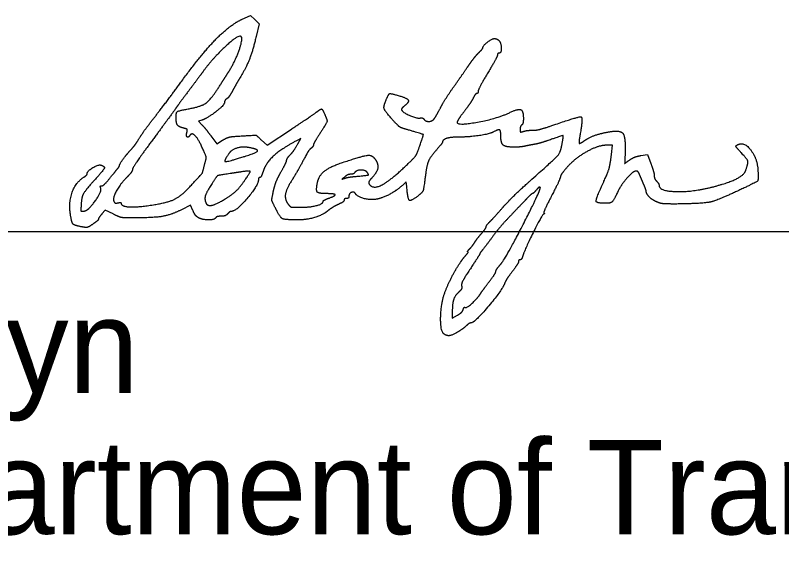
# Model space of a CAD drawing. Extents: x -6.1 to 38, y -7.7 to 22.
# Drawn here: x 26.554 to 27.692, y 4.883 to 5.697 of the extents above; entities that cross this region are included whole.
import ezdxf

# ---------------------------------------------------------------- set-up
doc = ezdxf.new("R2010")
doc.units = 0
for name, color, linetype in [('Default', 7, 'Continuous'), ('SH_Data', 7, 'Continuous'), ('SH_Text', 7, 'Continuous')]:
    doc.layers.add(name, color=color, linetype=linetype)

msp = doc.modelspace()

# ---------------------------------------------------------------- linework, layer by layer
at = {"layer": 'Default'}
for points in [[(26.8904, 5.6908), (26.903, 5.6966), (26.9094, 5.6903), (26.9158, 5.6839), (26.9114, 5.6652)], [(26.8305, 5.5408), (26.8255, 5.5392), (26.8306, 5.5341)], [(26.9194, 5.5111), (26.9276, 5.5035), (26.9638, 5.5276)], [(26.8443, 5.5174), (26.8528, 5.5059), (26.8616, 5.5111)], [(26.9733, 5.5058), (26.9778, 5.5138), (26.9723, 5.5108)], [(27.4392, 5.4899), (27.4407, 5.5037), (27.4329, 5.5037)], [(27.483, 5.4883), (27.4927, 5.4899), (27.4978, 5.4763)], [(27.1351, 5.4422), (27.1344, 5.449), (27.1286, 5.4439)], [(26.8175, 5.4066), (26.8141, 5.4146), (26.8003, 5.4077)], [(26.6988, 5.4015), (26.6873, 5.4073), (26.6823, 5.4015)], [(27.2028, 5.256), (27.2028, 5.2467), (27.2104, 5.251)]]:
    msp.add_lwpolyline(points, dxfattribs=at)
for points in [[(26.8008, 5.5989), (26.8305, 5.6395), (26.8723, 5.6824), (26.8904, 5.6908)], [(26.889, 5.665), (26.8853, 5.6686), (26.8468, 5.6329), (26.8314, 5.6116)], [(26.8707, 5.6129), (26.8801, 5.6278), (26.8921, 5.6619), (26.889, 5.665)], [(26.9114, 5.6652), (26.9064, 5.6441), (26.8972, 5.6205), (26.8878, 5.6045)], [(27.2484, 5.6489), (27.2484, 5.6517), (27.2616, 5.662), (27.2654, 5.6621)], [(27.2654, 5.6621), (27.2674, 5.6621), (27.2704, 5.6608), (27.272, 5.6593)], [(27.272, 5.6593), (27.2754, 5.6558), (27.2758, 5.6405), (27.2724, 5.6405)], [(27.2418, 5.6408), (27.2455, 5.6444), (27.2484, 5.648), (27.2484, 5.6489)], [(27.2281, 5.6235), (27.232, 5.6294), (27.2382, 5.6371), (27.2418, 5.6408)], [(27.27, 5.638), (27.27, 5.6366), (27.2636, 5.6245), (27.2556, 5.6111)], [(27.2724, 5.6405), (27.2711, 5.6405), (27.27, 5.6394), (27.27, 5.638)], [(27.2064, 5.5925), (27.2144, 5.6038), (27.2241, 5.6177), (27.2281, 5.6235)], [(26.8314, 5.6116), (26.8278, 5.6066), (26.8184, 5.594), (26.8104, 5.5835)], [(26.8601, 5.5963), (26.8634, 5.6015), (26.8681, 5.609), (26.8707, 5.6129)], [(26.8878, 5.6045), (26.8842, 5.5986), (26.879, 5.5894), (26.8762, 5.5841)], [(27.2556, 5.6111), (27.2477, 5.5978), (27.2412, 5.5854), (27.2412, 5.5837)], [(26.7607, 5.5455), (26.7696, 5.5568), (26.7876, 5.5809), (26.8008, 5.5989)], [(26.8103, 5.5576), (26.8309, 5.5613), (26.845, 5.5723), (26.8601, 5.5963)], [(27.1851, 5.5589), (27.1889, 5.5662), (27.1985, 5.5813), (27.2064, 5.5925)], [(26.8104, 5.5835), (26.8025, 5.573), (26.7944, 5.562), (26.7924, 5.5591)], [(26.8762, 5.5841), (26.8733, 5.5789), (26.8695, 5.5737), (26.8677, 5.5726)], [(27.1044, 5.5708), (27.1081, 5.5798), (27.1113, 5.5808), (27.124, 5.5771)], [(27.2393, 5.5805), (27.2382, 5.5805), (27.2358, 5.5776), (27.234, 5.5739)], [(27.2412, 5.5837), (27.2412, 5.5819), (27.2403, 5.5805), (27.2393, 5.5805)], [(26.8677, 5.5726), (26.8659, 5.5716), (26.8644, 5.5691), (26.8644, 5.5672)], [(27.1142, 5.5413), (27.1027, 5.5544), (27.1004, 5.5612), (27.1044, 5.5708)], [(27.124, 5.5771), (27.136, 5.5736), (27.1388, 5.5674), (27.1312, 5.5615)], [(27.234, 5.5739), (27.2322, 5.5703), (27.2261, 5.5612), (27.2204, 5.5537)], [(26.7924, 5.5591), (26.7905, 5.5561), (26.7751, 5.5352), (26.7583, 5.5125)], [(26.7924, 5.5455), (26.7924, 5.5523), (26.7966, 5.5551), (26.8103, 5.5576)], [(26.8644, 5.5672), (26.8644, 5.5634), (26.8387, 5.5434), (26.8305, 5.5408)], [(27.0029, 5.5541), (27.0075, 5.5579), (27.0099, 5.557), (27.0129, 5.5504)], [(27.1312, 5.5615), (27.1284, 5.5594), (27.127, 5.5566), (27.1279, 5.5553)], [(27.1758, 5.5427), (27.1771, 5.5444), (27.1812, 5.5517), (27.1851, 5.5589)], [(27.2876, 5.5519), (27.3006, 5.5581), (27.3084, 5.5549), (27.3084, 5.5435)], [(26.7391, 5.5161), (26.7421, 5.5209), (26.7518, 5.5341), (26.7607, 5.5455)], [(26.8034, 5.5291), (26.7963, 5.5309), (26.7924, 5.5366), (26.7924, 5.5455)], [(26.9638, 5.5276), (26.9837, 5.5409), (27.0013, 5.5528), (27.0029, 5.5541)], [(27.0129, 5.5504), (27.0172, 5.5408), (27.0163, 5.5367), (27.006, 5.5208)], [(27.1279, 5.5553), (27.1306, 5.5515), (27.1505, 5.5433), (27.1551, 5.5441)], [(27.2204, 5.5537), (27.2147, 5.5463), (27.21, 5.539), (27.21, 5.5377)], [(27.21, 5.5377), (27.21, 5.5324), (27.2697, 5.5433), (27.2876, 5.5519)], [(27.3508, 5.5328), (27.3911, 5.5467), (27.3971, 5.5451), (27.3929, 5.5212)], [(26.8306, 5.5341), (26.8335, 5.5313), (26.8396, 5.5238), (26.8443, 5.5174)], [(27.1376, 5.5262), (27.1269, 5.5293), (27.122, 5.5325), (27.1142, 5.5413)], [(27.1551, 5.5441), (27.1574, 5.5445), (27.1599, 5.5436), (27.1608, 5.5423)], [(27.1608, 5.5423), (27.1629, 5.5388), (27.173, 5.5391), (27.1758, 5.5427)], [(27.306, 5.5337), (27.3047, 5.5329), (27.3036, 5.5301), (27.3036, 5.5274)], [(27.3084, 5.5435), (27.3084, 5.539), (27.3074, 5.5346), (27.306, 5.5337)], [(26.8085, 5.5228), (26.8095, 5.5264), (26.8082, 5.5279), (26.8034, 5.5291)], [(26.8128, 5.5181), (26.8104, 5.5142), (26.8072, 5.5177), (26.8085, 5.5228)], [(27.1544, 5.5025), (27.1601, 5.5193), (27.1597, 5.5198), (27.1376, 5.5262)], [(27.2634, 5.5231), (27.2578, 5.5201), (27.2276, 5.5157), (27.2127, 5.5157)], [(27.2748, 5.5184), (27.2748, 5.5257), (27.2712, 5.5272), (27.2634, 5.5231)], [(27.3036, 5.5274), (27.3036, 5.5235), (27.3047, 5.5229), (27.309, 5.5243)], [(27.309, 5.5243), (27.312, 5.5253), (27.3178, 5.5259), (27.322, 5.5258)], [(27.322, 5.5258), (27.3261, 5.5256), (27.3391, 5.5288), (27.3508, 5.5328)], [(27.3989, 5.5103), (27.4061, 5.5154), (27.4244, 5.5217), (27.438, 5.5239)], [(27.438, 5.5239), (27.4527, 5.5262), (27.4603, 5.5157), (27.4596, 5.4945)], [(26.7228, 5.4942), (26.7294, 5.5015), (26.7337, 5.5073), (26.7391, 5.5161)], [(26.7583, 5.5125), (26.7415, 5.4899), (26.7277, 5.4697), (26.7276, 5.4677)], [(26.8316, 5.4994), (26.8255, 5.5131), (26.8157, 5.5228), (26.8128, 5.5181)], [(26.8616, 5.5111), (26.8682, 5.515), (26.8757, 5.5167), (26.8909, 5.5175)], [(26.8909, 5.5175), (26.9112, 5.5187), (26.9113, 5.5187), (26.9194, 5.5111)], [(26.9723, 5.5108), (26.9489, 5.4983), (26.9261, 5.4776), (26.922, 5.4652)], [(27.006, 5.5208), (27.0008, 5.5127), (26.9964, 5.5051), (26.9964, 5.5039)], [(27.2127, 5.5157), (27.2012, 5.5157), (27.1884, 5.512), (27.1884, 5.5086)], [(27.2942, 5.5008), (27.2818, 5.5008), (27.2748, 5.5071), (27.2748, 5.5184)], [(27.3454, 5.5108), (27.3376, 5.5081), (27.328, 5.5054), (27.324, 5.5048)], [(27.3661, 5.5062), (27.3682, 5.5177), (27.3664, 5.5181), (27.3454, 5.5108)], [(27.3929, 5.5212), (27.3916, 5.5136), (27.3909, 5.5069), (27.3913, 5.5065)], [(26.8349, 5.4749), (26.8375, 5.4848), (26.8372, 5.487), (26.8316, 5.4994)], [(26.9026, 5.4998), (26.8918, 5.502), (26.8744, 5.4969), (26.8701, 5.4903)], [(26.892, 5.4863), (26.9113, 5.4922), (26.9153, 5.4973), (26.9026, 5.4998)], [(26.9605, 5.4877), (26.966, 5.4937), (26.9685, 5.4973), (26.9733, 5.5058)], [(26.9964, 5.5039), (26.9964, 5.5028), (26.9948, 5.5006), (26.9929, 5.499)], [(27.1361, 5.4752), (27.1466, 5.4852), (27.1507, 5.4914), (27.1544, 5.5025)], [(27.1884, 5.5086), (27.1884, 5.5077), (27.1842, 5.5023), (27.1791, 5.4965)], [(27.3108, 5.5022), (27.3075, 5.5014), (27.3, 5.5008), (27.2942, 5.5008)], [(27.324, 5.5048), (27.3201, 5.5041), (27.3141, 5.503), (27.3108, 5.5022)], [(27.3212, 5.4532), (27.3567, 5.4848), (27.3636, 5.4929), (27.3661, 5.5062)], [(27.4329, 5.5037), (27.4202, 5.5037), (27.3864, 5.4853), (27.3742, 5.4718)], [(27.3913, 5.5065), (27.3918, 5.506), (27.3952, 5.5077), (27.3989, 5.5103)], [(27.6296, 5.4951), (27.6243, 5.5008), (27.6241, 5.5034), (27.6287, 5.5052)], [(27.6287, 5.5052), (27.6373, 5.5085), (27.6558, 5.4836), (27.6568, 5.4673)], [(26.7084, 5.4737), (26.7084, 5.4754), (26.7176, 5.4884), (26.7228, 5.4942)], [(26.8701, 5.4903), (26.8631, 5.4796), (26.8676, 5.4788), (26.892, 5.4863)], [(26.986, 5.4897), (26.9779, 5.4743), (26.9701, 5.4605), (26.964, 5.4508)], [(26.9929, 5.499), (26.9909, 5.4974), (26.9878, 5.4932), (26.986, 5.4897)], [(27.0398, 5.478), (27.0717, 5.4886), (27.0851, 5.489), (27.0902, 5.4795)], [(27.1791, 5.4965), (27.1706, 5.487), (27.1649, 5.4745), (27.1633, 5.4617)], [(27.4245, 5.4421), (27.4336, 5.462), (27.4376, 5.4752), (27.4392, 5.4899)], [(27.4596, 5.4945), (27.4589, 5.4761), (27.4588, 5.4764), (27.4665, 5.4819)], [(27.4665, 5.4819), (27.4703, 5.4846), (27.4777, 5.4875), (27.483, 5.4883)], [(27.6388, 5.466), (27.6427, 5.4778), (27.6412, 5.4827), (27.6296, 5.4951)], [(26.9481, 5.4636), (26.9525, 5.4713), (26.9563, 5.4789), (26.9566, 5.4807)], [(26.9566, 5.4807), (26.9568, 5.4824), (26.9586, 5.4856), (26.9605, 5.4877)], [(27.0022, 5.4469), (27.0043, 5.4582), (27.0205, 5.4716), (27.0398, 5.478)], [(27.0902, 5.4795), (27.0934, 5.4735), (27.09, 5.4621), (27.0825, 5.4542)], [(26.6605, 5.4617), (26.6605, 5.4655), (26.6773, 5.4754), (26.6811, 5.474)], [(26.6811, 5.474), (26.687, 5.4717), (26.6848, 5.4668), (26.6704, 5.4509)], [(26.6939, 5.4545), (26.6993, 5.4611), (26.7047, 5.4678), (26.706, 5.4694)], [(26.706, 5.4694), (26.7074, 5.471), (26.7084, 5.473), (26.7084, 5.4737)], [(26.7276, 5.4677), (26.7276, 5.4658), (26.7242, 5.4609), (26.7203, 5.457)], [(26.8152, 5.4444), (26.8313, 5.462), (26.8317, 5.4625), (26.8349, 5.4749)], [(26.8952, 5.4525), (26.9031, 5.4639), (26.9021, 5.466), (26.8902, 5.4642)], [(26.922, 5.4652), (26.9203, 5.46), (26.918, 5.4557), (26.9169, 5.4557)], [(27.076, 5.4638), (27.0732, 5.4671), (27.0597, 5.4663), (27.0575, 5.4627)], [(27.0791, 5.4463), (27.0845, 5.4377), (27.1112, 5.4512), (27.1361, 5.4752)], [(27.3742, 5.4718), (27.3684, 5.4653), (27.3636, 5.4587), (27.3636, 5.4572)], [(27.4761, 5.4653), (27.4717, 5.4653), (27.4535, 5.4448), (27.4488, 5.4347)], [(27.4816, 5.4587), (27.4802, 5.4624), (27.4777, 5.4653), (27.4761, 5.4653)], [(27.4978, 5.4763), (27.5006, 5.4689), (27.5028, 5.4607), (27.5028, 5.4582)], [(27.5899, 5.4417), (27.6136, 5.448), (27.6365, 5.4594), (27.6388, 5.466)], [(27.6568, 5.4673), (27.6577, 5.452), (27.655, 5.4489), (27.6316, 5.4379)], [(26.6356, 5.4001), (26.6326, 5.4186), (26.6434, 5.4486), (26.6558, 5.4564)], [(26.6558, 5.4564), (26.6583, 5.458), (26.6605, 5.4604), (26.6605, 5.4617)], [(26.6816, 5.4432), (26.6831, 5.4429), (26.6886, 5.4479), (26.6939, 5.4545)], [(26.7203, 5.457), (26.7104, 5.4474), (26.6981, 5.4253), (26.6999, 5.4206)], [(26.8728, 5.4615), (26.8551, 5.4589), (26.853, 5.4578), (26.8458, 5.4466)], [(26.8902, 5.4642), (26.8846, 5.4633), (26.8768, 5.4621), (26.8728, 5.4615)], [(26.9169, 5.4557), (26.9158, 5.4557), (26.9148, 5.4544), (26.9148, 5.4527)], [(26.9372, 5.4358), (26.9388, 5.4434), (26.9437, 5.456), (26.9481, 5.4636)], [(27.0431, 5.4567), (27.0385, 5.453), (27.0385, 5.453), (27.0432, 5.4546)], [(27.052, 5.4605), (27.0497, 5.4605), (27.0457, 5.4588), (27.0431, 5.4567)], [(27.0432, 5.4546), (27.0459, 5.4556), (27.0534, 5.4568), (27.06, 5.4574)], [(27.0575, 5.4627), (27.0568, 5.4615), (27.0543, 5.4605), (27.052, 5.4605)], [(27.06, 5.4574), (27.0768, 5.4589), (27.0792, 5.4599), (27.076, 5.4638)], [(27.0825, 5.4542), (27.0798, 5.4513), (27.0783, 5.4477), (27.0791, 5.4463)], [(27.1633, 5.4617), (27.1604, 5.4392), (27.1587, 5.4337), (27.153, 5.4293)], [(27.3636, 5.4572), (27.3636, 5.4556), (27.3577, 5.4427), (27.3504, 5.4286)], [(27.4876, 5.4446), (27.4858, 5.4487), (27.4831, 5.4551), (27.4816, 5.4587)], [(27.5028, 5.4582), (27.5028, 5.4557), (27.5045, 5.4521), (27.5064, 5.4501)], [(26.6704, 5.4509), (26.6568, 5.4357), (26.6518, 5.4256), (26.6512, 5.4118)], [(26.6804, 5.4403), (26.6797, 5.4423), (26.6802, 5.4436), (26.6816, 5.4432)], [(26.7587, 5.4151), (26.7815, 5.4188), (26.8011, 5.429), (26.8152, 5.4444)], [(26.8458, 5.4466), (26.8376, 5.4339), (26.8344, 5.4241), (26.8366, 5.4183)], [(26.8654, 5.4238), (26.8765, 5.4308), (26.8875, 5.4413), (26.8952, 5.4525)], [(26.9148, 5.4527), (26.9147, 5.4442), (26.8816, 5.4053), (26.8744, 5.4053)], [(26.964, 5.4508), (26.956, 5.4382), (26.9537, 5.423), (26.9589, 5.4162)], [(27.0158, 5.4317), (27.0043, 5.4317), (27.0002, 5.4363), (27.0022, 5.4469)], [(27.1286, 5.4439), (27.1192, 5.4357), (27.0992, 5.4251), (27.09, 5.4234)], [(27.2772, 5.4105), (27.2844, 5.4189), (27.3042, 5.4381), (27.3212, 5.4532)], [(27.4909, 5.435), (27.4909, 5.4361), (27.4894, 5.4404), (27.4876, 5.4446)], [(27.5064, 5.4501), (27.5084, 5.4481), (27.51, 5.4454), (27.51, 5.4441)], [(27.51, 5.4441), (27.51, 5.4355), (27.5606, 5.4341), (27.5899, 5.4417)], [(26.656, 5.4058), (26.6623, 5.4067), (26.6824, 5.4351), (26.6804, 5.4403)], [(26.9392, 5.4118), (26.9347, 5.4209), (26.9345, 5.4231), (26.9372, 5.4358)], [(27.0191, 5.4248), (27.0294, 5.4285), (27.0279, 5.4317), (27.0158, 5.4317)], [(27.0588, 5.4319), (27.0567, 5.4352), (27.0492, 5.432), (27.0492, 5.4279)], [(27.09, 5.4234), (27.0814, 5.4218), (27.0616, 5.4272), (27.0588, 5.4319)], [(27.153, 5.4293), (27.1413, 5.4201), (27.1369, 5.4232), (27.1351, 5.4422)], [(27.2746, 5.3267), (27.2822, 5.3354), (27.3354, 5.4391), (27.3334, 5.4412)], [(27.3219, 5.4317), (27.3211, 5.4317), (27.3172, 5.4282), (27.3131, 5.4239)], [(27.3277, 5.4371), (27.3252, 5.4342), (27.3226, 5.4317), (27.3219, 5.4317)], [(27.3334, 5.4412), (27.3326, 5.4419), (27.3301, 5.4401), (27.3277, 5.4371)], [(27.4319, 5.4173), (27.4173, 5.4173), (27.4157, 5.4228), (27.4245, 5.4421)], [(27.4488, 5.4347), (27.443, 5.4223), (27.4382, 5.4173), (27.4319, 5.4173)], [(27.5066, 5.4194), (27.4995, 5.4227), (27.4911, 5.4311), (27.4909, 5.435)], [(27.6316, 5.4379), (27.5968, 5.4216), (27.5758, 5.4168), (27.5364, 5.4163)], [(26.6999, 5.4206), (26.7008, 5.4182), (26.7031, 5.4173), (26.7061, 5.418)], [(26.8366, 5.4183), (26.8386, 5.413), (26.8522, 5.4156), (26.8654, 5.4238)], [(26.9764, 5.4114), (26.9904, 5.4113), (27.0108, 5.4164), (27.0108, 5.42)], [(27.0108, 5.42), (27.0108, 5.421), (27.0146, 5.4232), (27.0191, 5.4248)], [(27.042, 5.4221), (27.042, 5.4207), (27.0396, 5.4185), (27.0366, 5.4172)], [(27.0456, 5.4245), (27.0437, 5.4245), (27.042, 5.4234), (27.042, 5.4221)], [(27.0492, 5.4279), (27.0492, 5.426), (27.0476, 5.4245), (27.0456, 5.4245)], [(27.3131, 5.4239), (27.309, 5.4196), (27.2985, 5.4086), (27.2897, 5.3993)], [(27.3504, 5.4286), (27.3431, 5.4145), (27.338, 5.4029), (27.339, 5.4029)], [(26.6512, 5.4118), (26.6509, 5.4062), (26.6517, 5.4051), (26.656, 5.4058)], [(26.7061, 5.418), (26.7087, 5.4187), (26.7108, 5.4184), (26.7108, 5.4173)], [(26.7108, 5.4173), (26.7108, 5.4126), (26.7365, 5.4115), (26.7587, 5.4151)], [(26.9709, 5.3926), (26.9534, 5.3927), (26.9464, 5.3969), (26.9392, 5.4118)], [(26.9589, 5.4162), (26.9617, 5.4123), (26.9653, 5.4114), (26.9764, 5.4114)], [(27.0366, 5.4172), (27.0293, 5.4139), (27.0217, 5.4093), (27.0174, 5.4058)], [(27.2587, 5.3901), (27.2616, 5.3929), (27.2699, 5.4021), (27.2772, 5.4105)], [(27.5364, 5.4163), (27.5215, 5.4162), (27.5112, 5.4172), (27.5066, 5.4194)], [(26.6522, 5.3824), (26.6413, 5.3844), (26.6374, 5.3885), (26.6356, 5.4001)], [(26.6823, 5.4015), (26.6795, 5.3983), (26.6772, 5.3949), (26.6772, 5.3939)], [(26.7296, 5.3957), (26.714, 5.3957), (26.7081, 5.3968), (26.6988, 5.4015)], [(26.8003, 5.4077), (26.7847, 5.4), (26.7595, 5.3957), (26.7296, 5.3957)], [(26.8257, 5.3959), (26.823, 5.3974), (26.8193, 5.4021), (26.8175, 5.4066)], [(26.8595, 5.3981), (26.8558, 5.3981), (26.8521, 5.3971), (26.8512, 5.3957)], [(26.8692, 5.4017), (26.8676, 5.3998), (26.8632, 5.3981), (26.8595, 5.3981)], [(26.8744, 5.4053), (26.8732, 5.4053), (26.8709, 5.4037), (26.8692, 5.4017)], [(27.0174, 5.4058), (27.0098, 5.3995), (26.9854, 5.3925), (26.9709, 5.3926)], [(27.2897, 5.3993), (27.2808, 5.39), (27.2709, 5.3788), (27.2676, 5.3743)], [(27.3383, 5.4011), (27.3356, 5.3993), (27.3103, 5.3483), (27.3074, 5.3387)], [(27.339, 5.4029), (27.34, 5.4029), (27.3397, 5.4021), (27.3383, 5.4011)], [(26.6689, 5.3865), (26.6623, 5.382), (26.6587, 5.3811), (26.6522, 5.3824)], [(26.6772, 5.3939), (26.6772, 5.3929), (26.6735, 5.3896), (26.6689, 5.3865)], [(26.8512, 5.3957), (26.8493, 5.3925), (26.8318, 5.3927), (26.8257, 5.3959)], [(27.2533, 5.3829), (27.2533, 5.384), (27.2557, 5.3872), (27.2587, 5.3901)], [(27.2676, 5.3743), (27.2596, 5.3634), (27.2491, 5.3496), (27.2461, 5.346)], [(27.2466, 5.373), (27.2503, 5.3773), (27.2533, 5.3817), (27.2533, 5.3829)], [(27.2364, 5.3597), (27.2384, 5.3628), (27.243, 5.3688), (27.2466, 5.373)], [(27.2286, 5.3497), (27.231, 5.3522), (27.2345, 5.3567), (27.2364, 5.3597)], [(27.1927, 5.2873), (27.1985, 5.3022), (27.2157, 5.3321), (27.2228, 5.3399)], [(27.2228, 5.3399), (27.2255, 5.3429), (27.227, 5.3453), (27.2261, 5.3453)], [(27.2261, 5.3453), (27.2252, 5.3453), (27.2263, 5.3473), (27.2286, 5.3497)], [(27.2436, 5.3421), (27.2436, 5.3416), (27.2373, 5.3317), (27.2296, 5.32)], [(27.2461, 5.346), (27.2447, 5.3444), (27.2436, 5.3427), (27.2436, 5.3421)], [(27.3012, 5.3308), (27.3012, 5.3295), (27.297, 5.3227), (27.2918, 5.3158)], [(27.3035, 5.3333), (27.3023, 5.3333), (27.3012, 5.3322), (27.3012, 5.3308)], [(27.3074, 5.3387), (27.3065, 5.3358), (27.3047, 5.3333), (27.3035, 5.3333)], [(27.2296, 5.32), (27.2209, 5.307), (27.2159, 5.2972), (27.2167, 5.2945)], [(27.2676, 5.3164), (27.2676, 5.3177), (27.2708, 5.3223), (27.2746, 5.3267)], [(27.2574, 5.3005), (27.2631, 5.3079), (27.2676, 5.315), (27.2676, 5.3164)], [(27.2918, 5.3158), (27.2866, 5.3089), (27.2814, 5.3009), (27.2804, 5.2981)], [(27.2167, 5.2945), (27.2173, 5.292), (27.2158, 5.2884), (27.213, 5.2859)], [(27.2804, 5.2981), (27.2767, 5.2882), (27.2356, 5.2397), (27.2309, 5.2397)], [(27.2448, 5.2833), (27.2462, 5.2854), (27.2518, 5.2931), (27.2574, 5.3005)], [(27.1908, 5.2229), (27.1849, 5.2267), (27.1862, 5.271), (27.1927, 5.2873)], [(27.213, 5.2859), (27.207, 5.2807), (27.2028, 5.2684), (27.2028, 5.256)], [(27.222, 5.2625), (27.224, 5.2613), (27.2406, 5.2765), (27.2448, 5.2833)], [(27.219, 5.2595), (27.2197, 5.2618), (27.221, 5.2632), (27.222, 5.2625)], [(27.2104, 5.251), (27.2145, 5.2534), (27.2184, 5.2572), (27.219, 5.2595)], [(27.2309, 5.2397), (27.2295, 5.2397), (27.2261, 5.2377), (27.2234, 5.2352)], [(27.2234, 5.2352), (27.2172, 5.2295), (27.2013, 5.2205), (27.1974, 5.2206)], [(27.1974, 5.2206), (27.1958, 5.2206), (27.1928, 5.2216), (27.1908, 5.2229)]]:
    msp.add_open_spline(points, degree=2, dxfattribs=at)
at = {"layer": 'SH_Data'}
msp.add_line((25.4051, 5.3756), (28.9051, 5.3756), dxfattribs=at)

# ---------------------------------------------------------------- texts
at = {"layer": 'SH_Text'}
for s, p in [('Pamela Boratyn', (25.4051, 5.1356)), ('Director, Department of Transportation', (25.4051, 4.9256))]:
    msp.add_text(s, height=0.14, dxfattribs=at).set_placement(p)

doc.saveas('drawing.dxf')
